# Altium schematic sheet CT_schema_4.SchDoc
size 349 x 342 mm
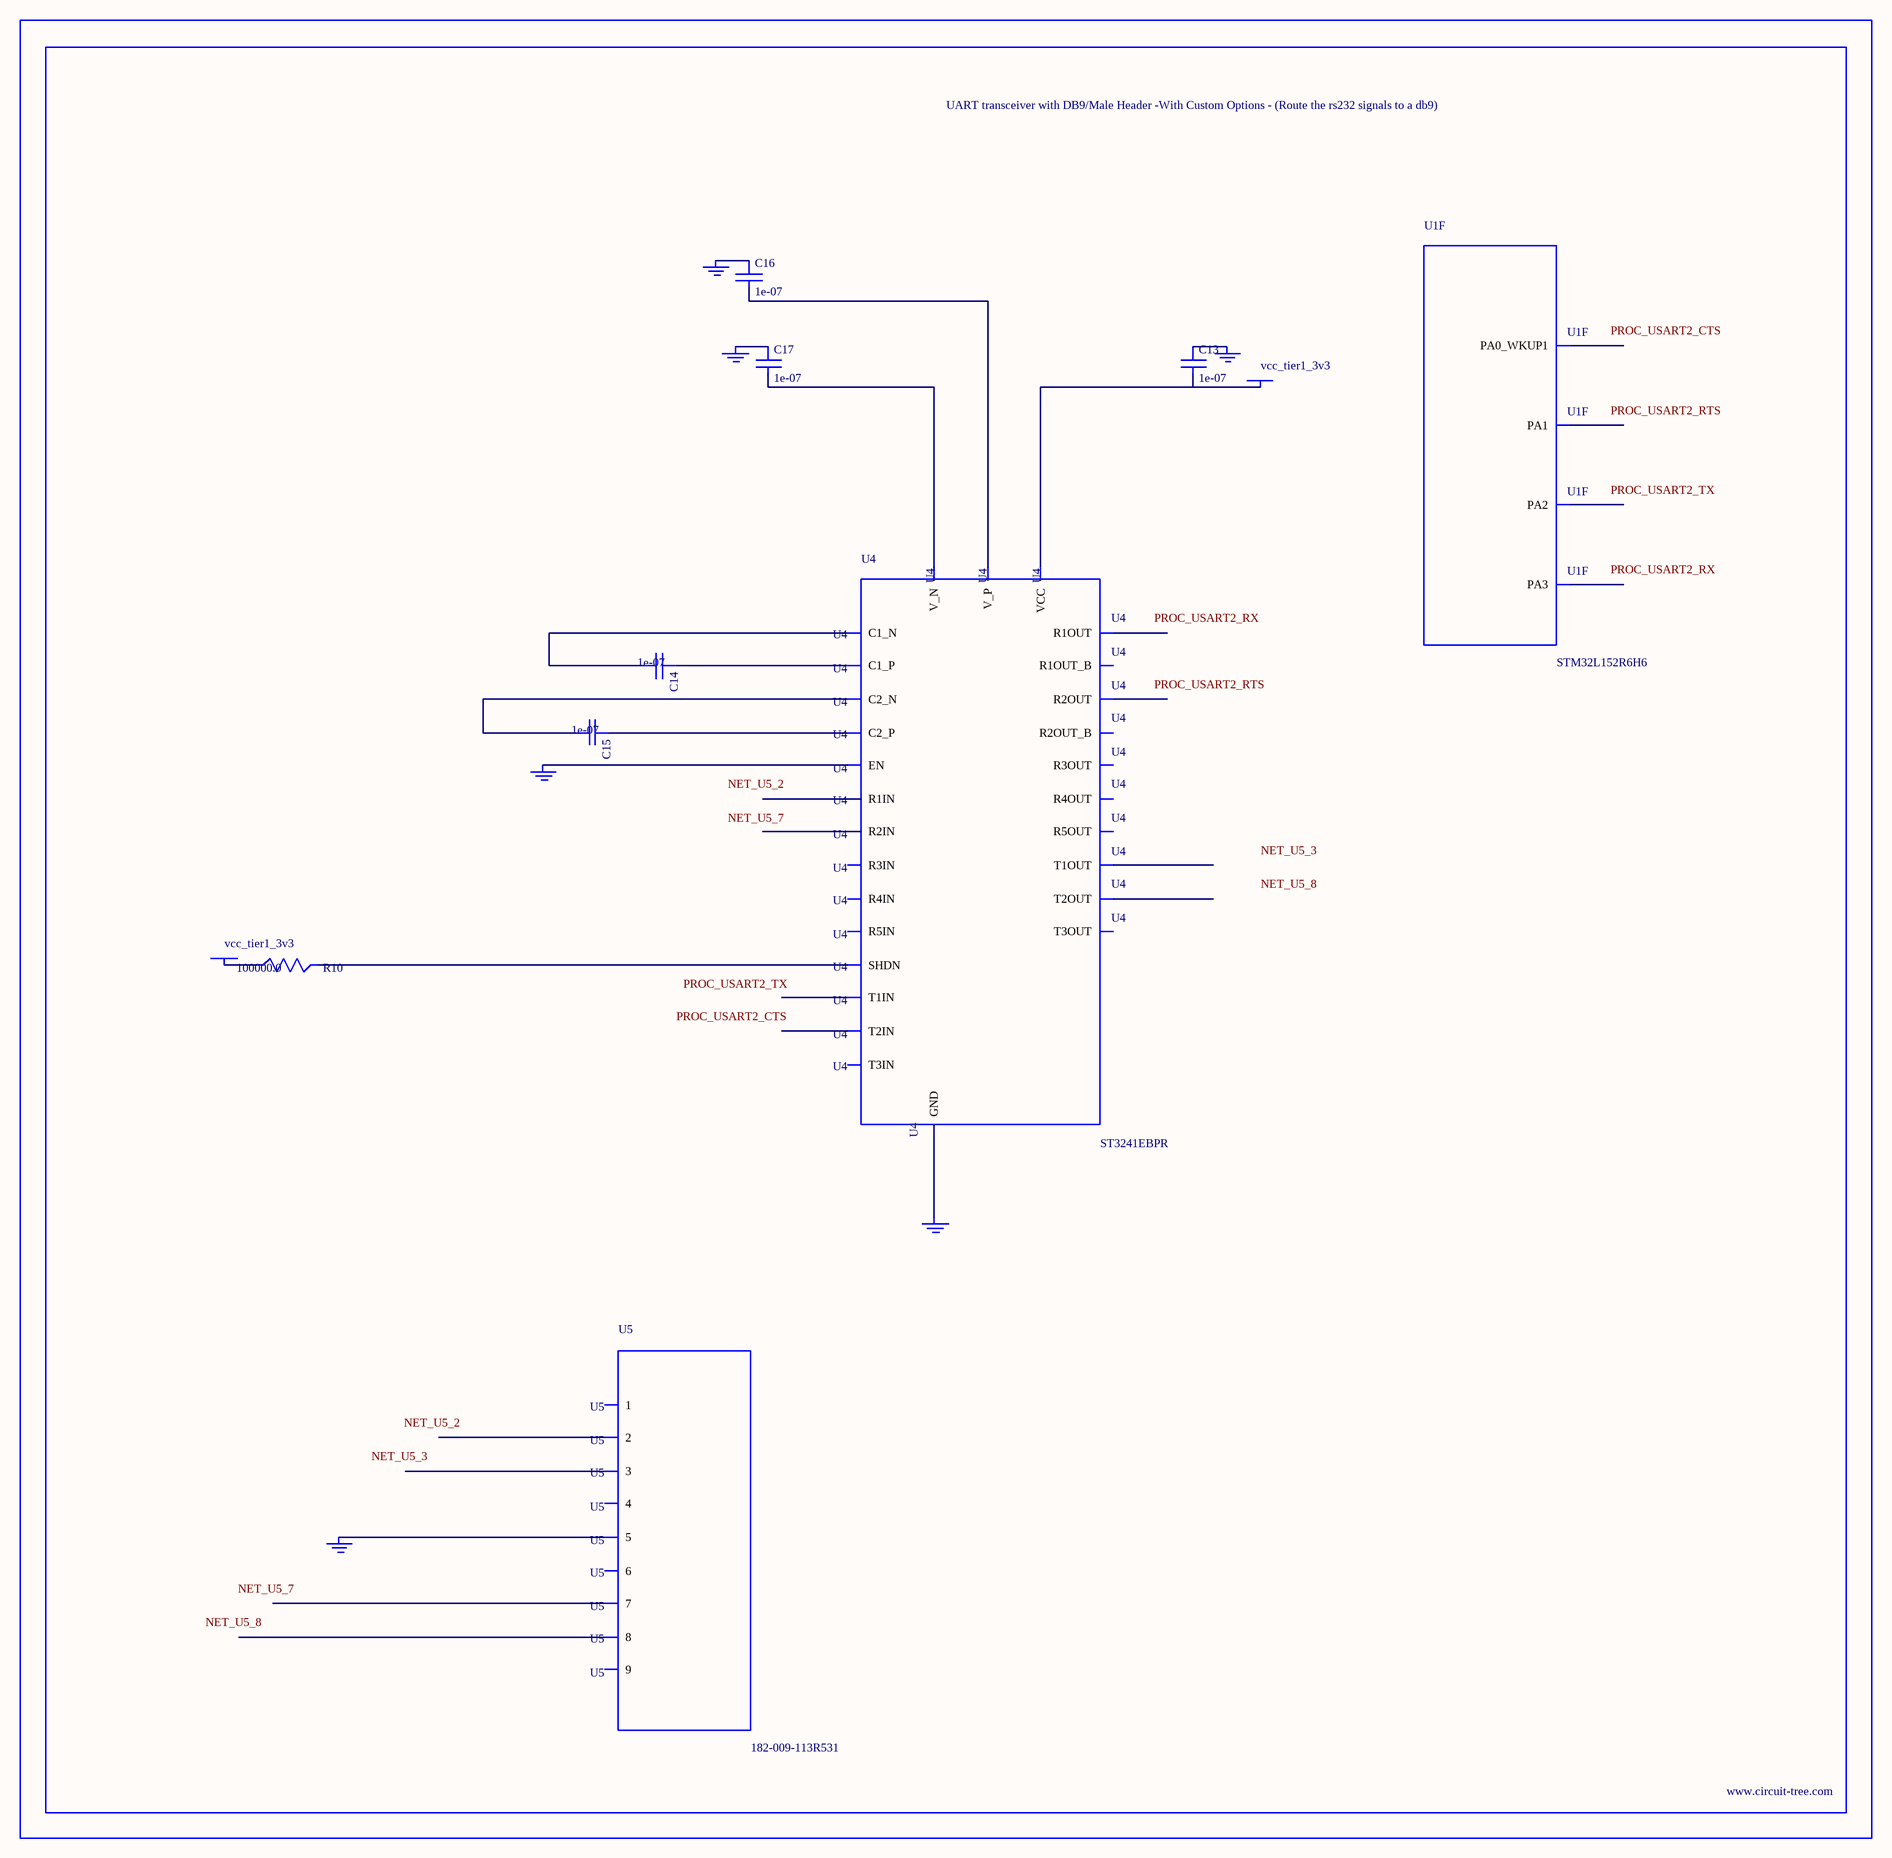
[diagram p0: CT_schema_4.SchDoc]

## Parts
BORDER3  (no value)
C13  1e-07  [C0402]
C14  1e-07  [C0402]
C15  1e-07  [C0402]
C16  1e-07  [C0402]
C17  1e-07  [C0402]
GND_INSTANCE_3_0  (no value)
GND_INSTANCE_3_1  (no value)
GND_INSTANCE_3_2  (no value)
GND_INSTANCE_3_3  (no value)
GND_INSTANCE_3_4  (no value)
GND_INSTANCE_3_5  (no value)
POWER_INSTANCE_3_0  vcc_tier1_3v3
POWER_INSTANCE_3_1  vcc_tier1_3v3
R10  100000.0  [R0603]
U1  STM32L152R6H6  [TFBGA64]  (part F of 7)
U4  ST3241EBPR  [SSOP-28]
U5  182-009-113R531  [182-009-MALE]

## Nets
NetC13_1: C13.1 GND_INSTANCE_3_2.0(GND)
NetC13_2: C13.2 POWER_INSTANCE_3_1.0(PWR) U4.26(VCC)
NetC14_1: C14.1 U4.28(C1_P)
NetC14_2: C14.2 U4.24(C1_N)
NetC15_1: C15.1 U4.1(C2_P)
NetC15_2: C15.2 U4.2(C2_N)
NetC16_1: C16.1 GND_INSTANCE_3_3.0(GND)
NetC16_2: C16.2 U4.27(V_P)
NetC17_1: C17.1 GND_INSTANCE_3_0.0(GND)
NetC17_2: C17.2 U4.3(V_N)
NetGND_INSTANCE_3_1_0: GND_INSTANCE_3_1.0(GND) U4.23(EN)
NetGND_INSTANCE_3_4_0: GND_INSTANCE_3_4.0(GND) U4.25(GND)
NetGND_INSTANCE_3_5_0: GND_INSTANCE_3_5.0(GND) U5.5
NetPOWER_INSTANCE_3_0_0: POWER_INSTANCE_3_0.0(PWR) R10.1
NetR10_2: R10.2 U4.22(SHDN)

Not connected (* = marked no-connect by the designer): U1 F3(PA2) G2(PA0_WKUP1) G3(PA3) H2(PA1); U4 4(R1IN) 5(R2IN) 6(R3IN) 7(R4IN) 8(R5IN) 9(T1OUT) 10(T2OUT) 11(T3OUT) 12(T3IN) 13(T2IN) 14(T1IN) 15(R5OUT) 16(R4OUT) 17(R3OUT) 18(R2OUT) 19(R1OUT) 20(R2OUT_B) 21(R1OUT_B); U5 1 2 3 4 6 7 8 9

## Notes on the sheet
- Labels drawn without touching a wire or pin: NET_U5_2, NET_U5_3, NET_U5_7, NET_U5_8, PROC_USART2_CTS, PROC_USART2_RTS, PROC_USART2_RX, PROC_USART2_TX

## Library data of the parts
BORDER3 = BORDER_PAGE3
C13-C17 = C0402C104K3RACTU
GND_INSTANCE_3_0-GND_INSTANCE_3_5 = GND
POWER_INSTANCE_3_0 POWER_INSTANCE_3_1 = PWR
R10 = RC0603JR-07100KL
